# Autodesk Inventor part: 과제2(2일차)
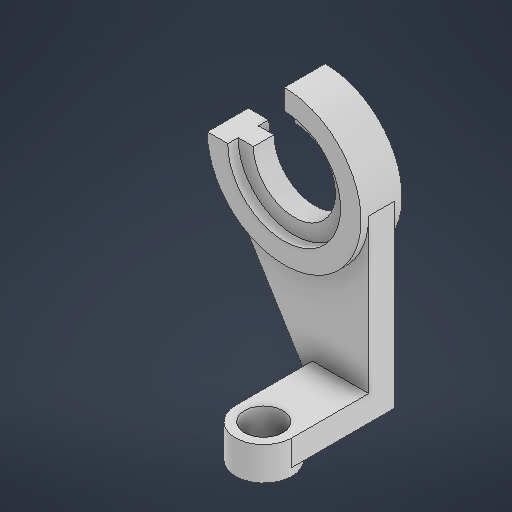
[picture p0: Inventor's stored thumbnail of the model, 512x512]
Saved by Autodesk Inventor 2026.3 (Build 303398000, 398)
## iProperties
Created: 2026-08
Part Number: 과제2(2일차)
Material: 일반
Document SubType Name: Modeling
Designer: chang
Density: 1 g/cm^3
Appearance: 기본값
Author: chang
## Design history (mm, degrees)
sketch "스케치1"
  geometry: L1 (0, 0)-(22, 0); L2 (22, 0)-(22, 70); L3 (-33.519, 54.226)-(0, 0) reference; L4 (-38, 70)-(-24, 70) reference; L5 (-8, 86)-(-8, 100) reference; A1 r 16 centre (-8, 70) between (-24, 70) and (-8, 86); A2 r 30 centre (-8, 70) between (-38, 70) and (-33.519, 54.226); A3 r 30 centre (-8, 70) between (22, 70) and (-8, 100)
  constraints: 10 end point, 6 point on circle, 3 centre point, 3 horizontal, 2 perpendicular, 2 tangent, 1 coincident, 1 vertical, 1 other
  dimensions: "d0" = 22 distance of L1.start L1.end; "d1" = 70 distance of L1.end L2.end; "d4" = 30 horizontal distance of L2.end L5.end; "d5" = 16 horizontal distance of L5.start L4.end
extrude "돌출1" new body sketch "스케치1" stored distance "d6" = 8; taper "d7" = 0 deg
sketch "스케치2"
  geometry: L1 (-33.519, 54.226)-(0, 0) reference; L2 (-33.519, 54.226)-(0, 0); L3 (22, 70)-(22, 0) reference; L4 (0, 0)-(22, 0); L5 (22, 0)-(22, 70) reference; L6 (22, 0)-(22, 70); A1 r 16 centre (-8, 70) between (-24, 70) and (-8, 86) reference; A2 r 30 centre (-8, 70) between (-33.519, 54.226) and (22, 70) reference
  constraints: 6 end point, 2 point on circle, 1 centre point, 1 collinear, 1 perpendicular, 1 point on line, 1 tangent, 1 other
extrude "돌출2" join sketch "스케치2" distance "d10" = 1; taper "d11" = 0 deg
sketch "스케치3"
  geometry: L1 (-38, 70)-(-30, 70) reference; L2 (-8, 86)-(-8, 100) reference; L3 (-8, 92)-(-8, 100); A1 r 16 centre (-8, 70) between (-24, 70) and (-8, 86) reference; A2 r 22 centre (-8, 70) between (-30, 70) and (-8, 92) reference; A3 r 30 centre (-8, 70) between (-38, 70) and (-8, 100); 5 further points
  constraints: 4 end point, 4 point on circle, 3 midpoint, 2 centre point, 2 coincident, 2 horizontal, 1 collinear, 4 other
extrude "돌출3" join sketch "스케치3" distance "d14" = 4; taper "d15" = 0 deg
sketch "스케치4"
  geometry: L1 (-22, 70)-(-22, 0); L2 (-22, 0)-(0, 0); L3 (0, 0)-(33.519, 54.226); A1 r 16 centre (8, 70) between (8, 86) and (24, 70) reference; A2 r 30 centre (8, 70) between (-22, 70) and (33.519, 54.226) reference; A3 r 30 centre (8, 70) between (-22, 70) and (33.519, 54.226) reference
  constraints: 6 end point, 2 point on circle, 2 tangent, 1 centre point, 1 perpendicular, 1 vertical, 1 other
extrude "돌출4" join sketch "스케치4" distance "d18" = 1; taper "d19" = 0 deg
sketch "스케치5"
  geometry: L1 (8, 100)-(8, 92) reference; L2 (30, 70)-(38, 70) reference; A1 r 16 centre (8, 70) between (8, 86) and (24, 70) reference; A2 r 22 centre (8, 70) between (8, 92) and (30, 70); A3 r 30 centre (8, 70) between (8, 100) and (38, 70) reference; 1 further point
  constraints: 4 end point, 4 point on circle, 2 centre point, 2 coincident, 2 vertical, 1 horizontal, 1 perpendicular, 1 other
  dimensions: "d20" = 44 diameter of A2
extrude "돌출5" join sketch "스케치5" distance "d22" = 4; taper "d23" = 0 deg
sketch "스케치6"
  geometry: 1 further point
sketch "스케치7"
  geometry: 1 further point
sketch "스케치8"
  geometry: 1 further point
sketch "스케치9"
  geometry: L1 (22, -10)-(22, 0) reference; L2 (22, 0)-(22, 30); L3 (0, 0)-(22, 0) reference; L4 (22, 0)-(0, 0); L5 (0, 0)-(0, 30); A1 r 11 centre (11, 30) between (0, 30) and (22, 30); 1 further point
  constraints: 6 end point, 2 point on circle, 2 vertical, 1 centre point, 1 collinear
  dimensions: "d24" = 30 distance of L1.end L2.end; "d25" = 30 distance of L3.start L5.end; "d26" = 22 diameter of A1
extrude "돌출6" join sketch "스케치9" distance "d27" = 10; taper "d28" = 0 deg
sketch "스케치10"
  geometry: C1 r 11 at (11, 40); C2 r 7.5 at (11, 40); A1 r 11 centre (11, 40) between (0, 40) and (22, 40) reference; 3 further points
  constraints: 2 centre point, 2 coincident
  dimensions: "d29" = 22 diameter of C1; "d30" = 15 diameter of C2
extrude "돌출7" join sketch "스케치10" distance "d31" = 10; taper "d32" = 0 deg
sketch "스케치11"
  geometry: 1 further point
sketch "스케치12"
  geometry: C1 r 7.5 at (11, 40) reference; C2 r 7.5 at (11, 40); C3 r 11 at (11, 40); 1 further point
  constraints: 2 centre point, 2 coincident
  dimensions: "d33" = 15 diameter of C2; "d34" = 22 diameter of C3
extrude "돌출8" join sketch "스케치12" distance "d35" = 3; taper "d36" = 0 deg
node "솔리드1"
